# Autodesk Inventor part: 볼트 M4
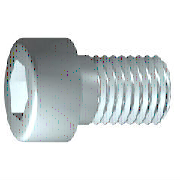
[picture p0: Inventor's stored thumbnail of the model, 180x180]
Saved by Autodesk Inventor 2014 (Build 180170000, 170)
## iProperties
IsCustomPart: 1
Created: 2012-02
Part Number: 볼트 M4
Material: 스테인리스강
Description: 6각 소켓 머리 캡 나사
Document SubType Name: Modeling
Standard: ISO 4762
Designer: mduedu
Standard Revision: Fourth edition 2004-03-01
Standards Organization: ISO
Language: ko-KR
Size Designation: M4 x 10
Categories: <MemberInstance><Categories><Category DisplayName="조임쇠" InternalName="e4da775c-781d-43d5-af7c-5136215cf5a6" Mnemonic="FSTN"><Category DisplayName="볼트" InternalN
Density: 7.75 g/cm^3
Appearance: 반광택
Author: mduedu
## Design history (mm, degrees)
sketch "스케치1"
  geometry: L1 (-1, 0)-(10, 0); L2 (10, 0)-(10, 2); L3 (10, 2)-(1.75, 2); L4 (1.75, 2)-(1.32, 2); L5 (1.32, 2)-(0, 2); L6 (0, 2)-(0, 3.5); L7 (0, 3.5)-(-4, 3.5); L8 (-4, 3.5)-(-4, 1.732); L9 (-4, 1.732)-(-2, 1.732); L10 (-2, 1.732)-(-1, 0); L11 (-6.8, 0)-(12.8, 0) reference; L12 (0, -0.7)-(0, 4.2) reference; L13 (1.75, 2)-(0, 2)
  constraints: 22 end point, 6 parallel, 2 collinear, 2 perpendicular, 1 horizontal, 1 point on line
  dimensions: "d1" = 8.25 distance from line of L3.end L2 (= GEL); "d2" = 0.42952 distance of L4.end L3.end (computed from GAL); "d3" = 4 distance between parallel lines of L8 L6 (= KOH); "d4" = 2 distance of L8.end L9.end (= INTI); "d5" = 60 deg angle of L10 L1; "d6" = 4 diameter of L3 L1 (= GD); "d7" = 4 diameter of L5 L1 (= BDM); "d8" = 3.4641 diameter of L9 L1 (= 1.1547 x SW); "d9" = 7 diameter of L7 L1 (= KOD); "d26" = 10 distance between parallel lines of L12 L2 (= NLG)
revolve "본체" sketch "스케치1" stored, may be unused: angle "d10" = 90 deg
sketch "스케치2"
  geometry: L1 (0, -4.9)-(0, 4.9) reference; L2 (-4.9, 0)-(4.9, 0) reference; L3 (1.732, 0)-(0.866, -1.5); L4 (0.866, -1.5)-(-0.866, -1.5); L5 (-0.866, -1.5)-(-1.732, 0); L6 (-1.732, 0)-(-0.866, 1.5); L7 (-0.866, 1.5)-(0.866, 1.5); L8 (0.866, 1.5)-(1.732, 0); 2 further points
  constraints: 12 end point, 1 coincident, 1 horizontal alignment, 1 point on line, 12 other
extrude "슬롯" join sketch "스케치2" stored distance "d11" = 10; taper "d12" = 0 deg
workplane "Work Plane1"
body "Solid1"
fillet "모깎기1" dims "d17" = 0.4 (= RR)
feature "스레드" dims "d13" = 8.25 (= GEL), "d14" = 0
chamfer "모따기1" distance "d15" = 0.42941 (= -0.5 x SPD + 0.5 x GD); stored, may be unused: second distance "d16" = 0.42941 (= GUL), angle "d27" = 45 deg
other parameters: "GD" = 4 [user parameter; used in 2 equation terms], "NLG" = 10 [user parameter; used in 1 equation term], "GEL" = 8.25 [user parameter; used in 2 equation terms], "KOD" = 7 [user parameter; used in 1 equation term], "KOH" = 4 [user parameter; used in 1 equation term], "INTI" = 2 [user parameter; used in 1 equation term], "GAL" = 0.42941 (= 0.61345 x PTC) [user parameter; used in 1 equation term], "GUL" = 0.42941 (= 0.61345 x PTC) [user parameter; used in 1 equation term], "BDM" = 4 (= NND) [user parameter; used in 1 equation term], "SW" = 3 [user parameter; used in 2 equation terms], "RR" = 0.4 [user parameter; used in 1 equation term], "SPD" = 3.14117 (= NND - 1.2269 x PTC) [user parameter; used in 1 equation term], "d19" = 0, "d28" = 0, "d29" = 0, "R" = 0.1 [user parameter], "TOA" = 30 deg [user parameter], "GD1" = 3.14117 (= THREADDIA - 1.2269 x PTC) [user parameter], "THREADDIA" = 4 [user parameter; used in 1 equation term], "FAWI" = 45 deg [user parameter], "TPU" = 14.28571 (computed from PTC) [user parameter], "PTC" = 0.7 [user parameter; used in 5 equation terms], "NND" = 4 [user parameter; used in 2 equation terms], "E0" = 3.465 (= 1.155 x SW) [user parameter]
